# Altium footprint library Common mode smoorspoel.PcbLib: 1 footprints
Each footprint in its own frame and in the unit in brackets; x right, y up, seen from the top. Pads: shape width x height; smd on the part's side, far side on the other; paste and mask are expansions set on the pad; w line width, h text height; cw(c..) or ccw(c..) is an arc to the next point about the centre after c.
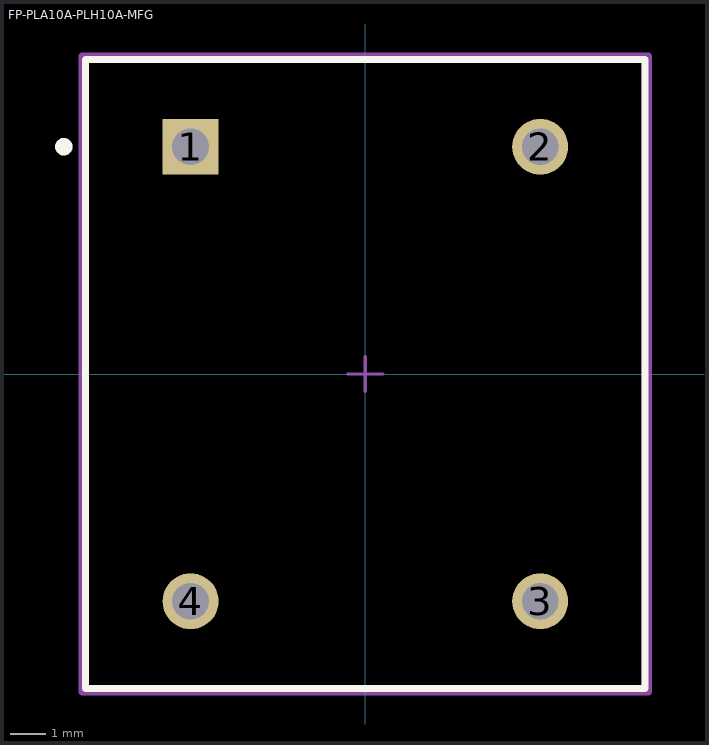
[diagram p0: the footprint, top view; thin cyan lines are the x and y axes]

## FP-PLA10A-PLH10A-MFG [mm]
pads (4):
  rect 1.6x1.6 hole 1.05 paste-2539.97 mask+0: 1(-5,6.5)
  round 1.6 hole 1.05 paste-2539.97 mask+0: 2(5,6.5) 3(5,-6.5) 4(-5,-6.5)
Top Overlay:
  circle w0.25: c-8.625,6.5 r0.125
  lines w0.2: -8,-9 -8,9 8,9 8,-9 -8,-9
Top Assembly:
  lines w0.2: -8.1,-9.1 -8.1,9.1 8.1,9.1 8.1,-9.1 -8.1,-9.1
  text ".Designator" at 0,0.188 h1
Top 3D Body:
  lines w0.2: -8,-9 -8,9 8,9 8,-9 -8,-9
Top Courtyard:
  lines w0.2: -8.1,-9.1 -8.1,9.1 8.1,9.1 8.1,-9.1 -8.1,-9.1
Top Component Center:
  lines w0.1: -0.5,0 0.5,0 ; 0,-0.5 0,0.5
3D body "Ind_Murata_PLH10AN1112R6P2B_eec.STEP": height 0.25, standoff 0, extent -8.1,-9.1 8.1,9.1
